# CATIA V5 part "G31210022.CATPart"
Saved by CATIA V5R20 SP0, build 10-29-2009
Part number: G31210022
Revision: 12
Definition: design
Nomenclature: G31210022
Source: made
Description: NOT SPECIFIED
Bounding box of the stored display mesh (mm): x -5 to 22, y -8 to 8, z -8 to 8
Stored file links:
  C:\Users\Raffaele\Desktop\3D X SITO CF\BOLEX\23-BUSH REF 312\G31210022.CATPart

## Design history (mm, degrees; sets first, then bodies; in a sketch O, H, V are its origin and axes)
Body1 "MANIFOLD_SOLID_BREP #5459" (main body)
  Solid1: solid without history
Body2 "MANIFOLD_SOLID_BREP #5602"
  Solid2: solid without history
Body3 "MANIFOLD_SOLID_BREP #5745"
  Solid3: solid without history
Body4 "MANIFOLD_SOLID_BREP #5888"
  Solid4: solid without history
Body5 "MANIFOLD_SOLID_BREP #6031"
  Solid5: solid without history
Body6 "MANIFOLD_SOLID_BREP #6174"
  Solid6: solid without history
Body7 "MANIFOLD_SOLID_BREP #6317"
  Solid7: solid without history
Body8 "MANIFOLD_SOLID_BREP #6462"
  Solid8: solid without history
Body9 "MANIFOLD_SOLID_BREP #6607"
  Solid9: solid without history
Body10 "MANIFOLD_SOLID_BREP #6752"
  Solid10: solid without history
Body11 "MANIFOLD_SOLID_BREP #6897"
  Solid11: solid without history
Body12 "MANIFOLD_SOLID_BREP #7040"
  Solid12: solid without history
Body13 "MANIFOLD_SOLID_BREP #7183"
  Solid13: solid without history
Body14 "MANIFOLD_SOLID_BREP #7328"
  Solid14: solid without history
Body15 "MANIFOLD_SOLID_BREP #7473"
  Solid15: solid without history
Body16 "MANIFOLD_SOLID_BREP #7618"
  Solid16: solid without history
Body17 "MANIFOLD_SOLID_BREP #7763"
  Solid17: solid without history
Body18 "MANIFOLD_SOLID_BREP #7908"
  Solid18: solid without history
Body19 "MANIFOLD_SOLID_BREP #8053"
  Solid19: solid without history
Body20 "MANIFOLD_SOLID_BREP #8196"
  Solid20: solid without history
Body21 "MANIFOLD_SOLID_BREP #8339"
  Solid21: solid without history
Body22 "MANIFOLD_SOLID_BREP #8484"
  Solid22: solid without history
Body23 "MANIFOLD_SOLID_BREP #8627"
  Solid23: solid without history
Body24 "MANIFOLD_SOLID_BREP #8772"
  Solid24: solid without history
Body25 "MANIFOLD_SOLID_BREP #8917"
  Solid25: solid without history
Body26 "MANIFOLD_SOLID_BREP #9060"
  Solid26: solid without history
Body27 "MANIFOLD_SOLID_BREP #9203"
  Solid27: solid without history
Body28 "MANIFOLD_SOLID_BREP #9348"
  Solid28: solid without history
Body29 "MANIFOLD_SOLID_BREP #9493"
  Solid29: solid without history
Body30 "MANIFOLD_SOLID_BREP #9636"
  Solid30: solid without history
Body31 "MANIFOLD_SOLID_BREP #9781"
  Solid31: solid without history
Body32 "MANIFOLD_SOLID_BREP #9926"
  Solid32: solid without history
Body33 "MANIFOLD_SOLID_BREP #10069"
  Solid33: solid without history
Body34 "MANIFOLD_SOLID_BREP #10212"
  Solid34: solid without history
Body35 "MANIFOLD_SOLID_BREP #10355"
  Solid35: solid without history
Body36 "MANIFOLD_SOLID_BREP #10498"
  Solid36: solid without history
Body37 "MANIFOLD_SOLID_BREP #10643"
  Solid37: solid without history
Body38 "MANIFOLD_SOLID_BREP #10786"
  Solid38: solid without history
Body39 "MANIFOLD_SOLID_BREP #10931"
  Solid39: solid without history
Body40 "MANIFOLD_SOLID_BREP #11076"
  Solid40: solid without history
Body41 "MANIFOLD_SOLID_BREP #11219"
  Solid41: solid without history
